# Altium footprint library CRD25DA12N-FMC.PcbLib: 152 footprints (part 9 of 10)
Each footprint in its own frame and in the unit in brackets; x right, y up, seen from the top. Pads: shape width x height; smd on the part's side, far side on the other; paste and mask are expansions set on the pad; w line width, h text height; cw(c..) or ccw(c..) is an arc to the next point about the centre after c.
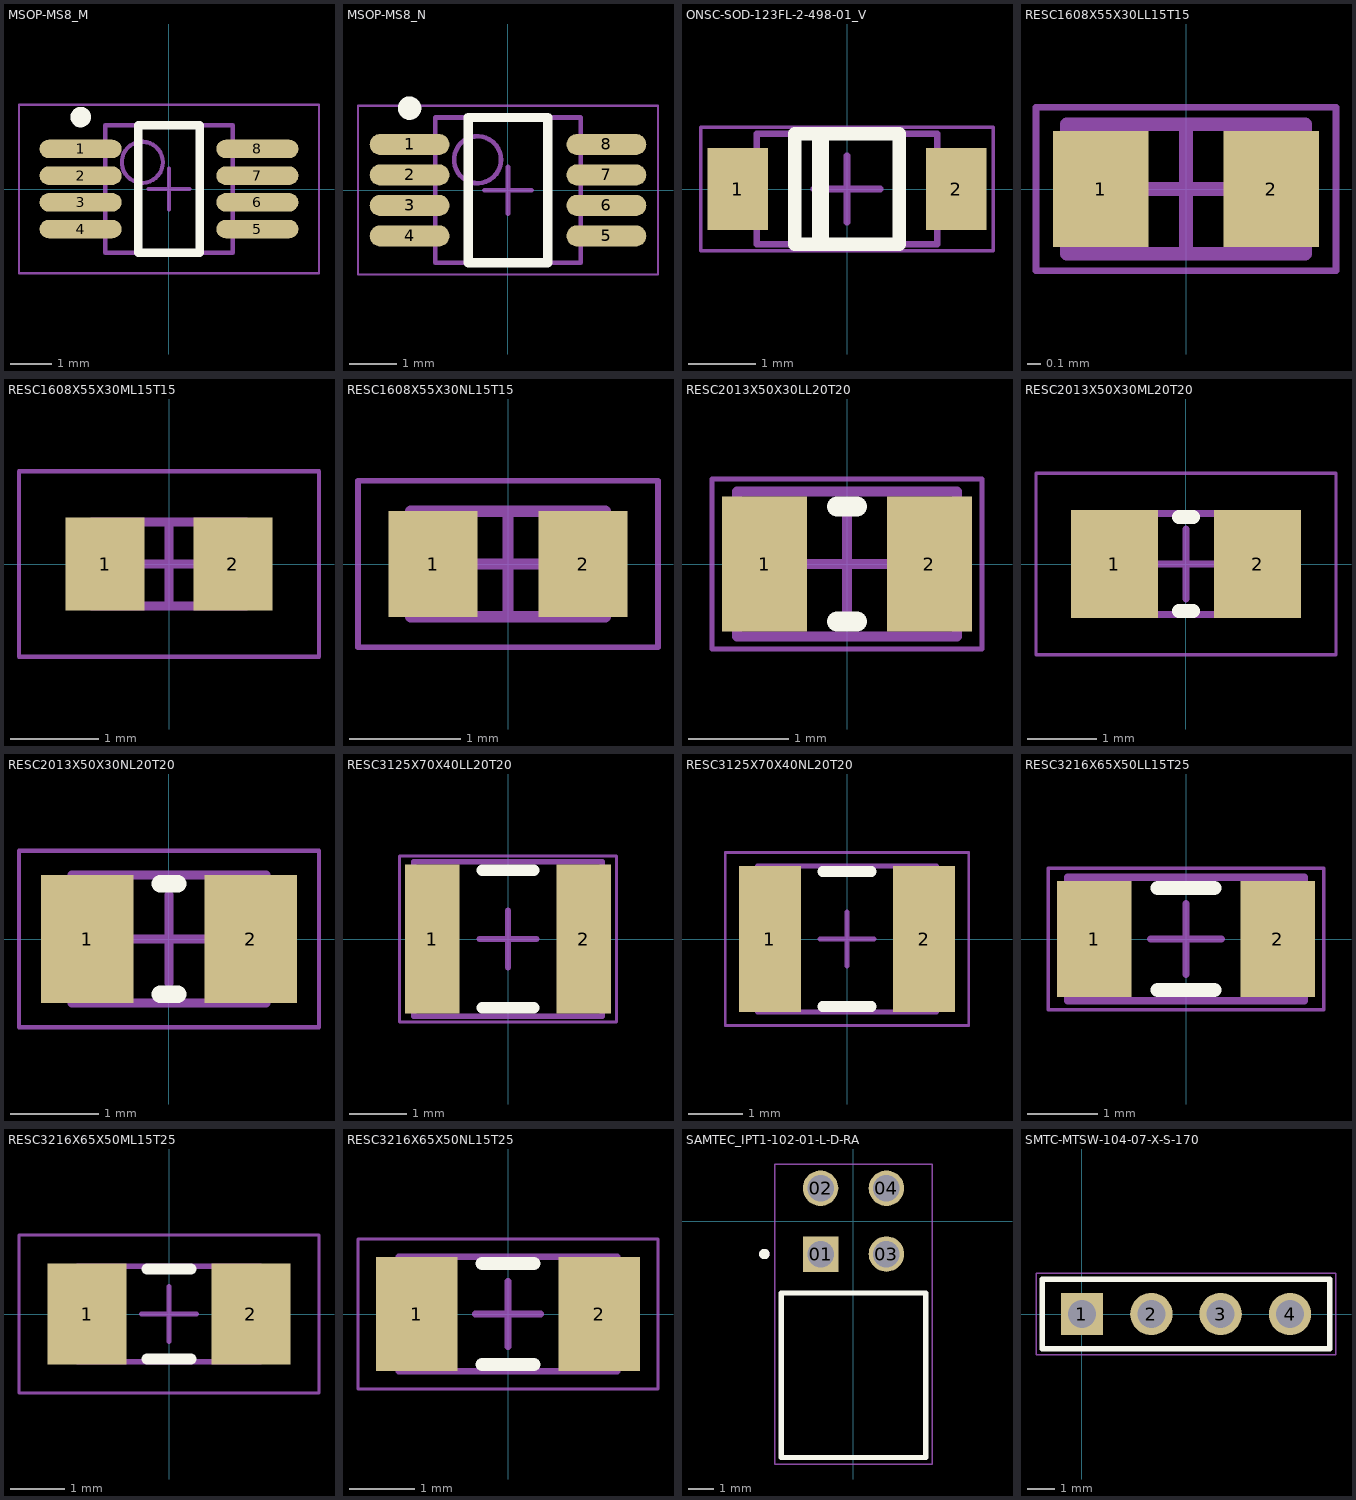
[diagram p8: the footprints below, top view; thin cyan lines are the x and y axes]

## MSOP-MS8_M [mm] "TSOP, 8-Leads, Body 3x3mm, Pitch 0.65mm, IPC Low Density"
height 1.1
pads (8):
  oval 2x0.45 smd: 1(-2.15,0.975) 2(-2.15,0.325) 3(-2.15,-0.325) 4(-2.15,-0.975) 5(2.15,-0.975) 6(2.15,-0.325) 7(2.15,0.325) 8(2.15,0.975)
Top Overlay:
  circle w0.25: c-2.15,1.75 r0.125
  lines w0.2: -0.75,-1.55 -0.75,1.55 0.75,1.55 0.75,-1.55 -0.75,-1.55
Mechanical 13:
  circle w0.1: c-0.65,0.65 r0.5
  lines w0.1: -1.55,-1.55 -1.55,1.55 1.55,1.55 1.55,-1.55 -1.55,-1.55
Mechanical 15:
  lines w0.05: -3.65,-2.05 -3.65,2.05 3.65,2.05 3.65,-2.05 -3.65,-2.05
  lines w0.1: -0.5,0 0.5,0 ; 0,-0.5 0,0.5
3D body: height 1.1, standoff 0, extent -1.55,-1.55 1.55,1.55

## MSOP-MS8_N [mm] "TSOP, 8-Leads, Body 3x3mm, Pitch 0.65mm, IPC Medium Density"
height 1.1
pads (8):
  oval 1.7x0.45 smd: 1(-2.1,0.975) 2(-2.1,0.325) 3(-2.1,-0.325) 4(-2.1,-0.975) 5(2.1,-0.975) 6(2.1,-0.325) 7(2.1,0.325) 8(2.1,0.975)
Top Overlay:
  circle w0.25: c-2.1,1.75 r0.125
  lines w0.2: -0.85,-1.55 0.85,-1.55 0.85,1.55 -0.85,1.55 -0.85,-1.55
Mechanical 13:
  circle w0.1: c-0.65,0.65 r0.5
  lines w0.1: -1.55,-1.55 1.55,-1.55 1.55,1.55 -1.55,1.55 -1.55,-1.55
Mechanical 15:
  lines w0.05: -3.2,-1.8 3.2,-1.8 3.2,1.8 -3.2,1.8 -3.2,-1.8
  lines w0.1: -0.5,0 0.5,0 ; 0,-0.5 0,0.5
3D body: height 1.1, standoff 0, extent -1.55,-1.55 1.55,1.55

## ONSC-SOD-123FL-2-498-01_V [mm] "SOD, 2-Leads, Body 2.7x1.65mm"
height 1
pads (2):
  rect 0.91x1.22 smd: 1(-1.635,0) 2(1.635,0)
Top Overlay:
  lines w0.2: -0.78,-0.825 -0.78,0.825 0.78,0.825 0.78,-0.825 -0.78,-0.825
  lines w0.254: -0.4,-0.78 -0.4,0.78
Mechanical 13:
  lines w0.1: -1.35,-0.825 -1.35,0.825 1.35,0.825 1.35,-0.825 -1.35,-0.825
Mechanical 15:
  lines w0.05: -2.19,-0.925 -2.19,0.925 2.19,0.925 2.19,-0.925 -2.19,-0.925
  lines w0.1: -0.5,0 0.5,0 ; 0,-0.5 0,0.5
3D body: height 1, standoff 0, extent -1.35,-0.825 1.35,0.825

## RESC1608X55X30LL15T15 [mm] "Chip Resistor, 2-Leads, Body 1.60x0.80mm, IPC High Density"
height 0.55
pads (2):
  rect 0.7x0.85 smd: 1(-0.625,0) 2(0.625,0)
Mechanical 13:
  lines w0.1: -0.875,-0.475 0.875,-0.475 0.875,0.475 -0.875,0.475 -0.875,-0.475
Mechanical 15:
  lines w0.05: -1.1,-0.6 1.1,-0.6 1.1,0.6 -1.1,0.6 -1.1,-0.6
  lines w0.1: -0.475,0 0.475,0 ; 0,-0.475 0,0.475
3D body: height 0.55, standoff 0, extent 0.575,-0.475 0.875,0.475
3D body: height 0.55, standoff 0, extent -0.875,-0.475 -0.575,0.475
3D body: height 0.55, standoff 0, extent -0.575,-0.475 0.575,0.475

## RESC1608X55X30ML15T15 [mm] "Chip Resistor, 2-Leads, Body 1.60x0.80mm, IPC Low Density"
height 0.55
pads (2):
  rect 0.9x1.05 smd: 1(-0.725,0) 2(0.725,0)
Mechanical 13:
  lines w0.1: -0.875,-0.475 0.875,-0.475 0.875,0.475 -0.875,0.475 -0.875,-0.475
Mechanical 15:
  lines w0.05: -1.7,-1.05 1.7,-1.05 1.7,1.05 -1.7,1.05 -1.7,-1.05
  lines w0.1: -0.475,0 0.475,0 ; 0,-0.475 0,0.475
3D body: height 0.55, standoff 0, extent 0.575,-0.475 0.875,0.475
3D body: height 0.55, standoff 0, extent -0.875,-0.475 -0.575,0.475
3D body: height 0.55, standoff 0, extent -0.575,-0.475 0.575,0.475

## RESC1608X55X30NL15T15 [mm] "Chip Resistor, 2-Leads, Body 1.60x0.80mm, IPC Medium Density"
height 0.55
pads (2):
  rect 0.8x0.95 smd: 1(-0.675,0) 2(0.675,0)
Mechanical 13:
  lines w0.1: -0.875,-0.475 0.875,-0.475 0.875,0.475 -0.875,0.475 -0.875,-0.475
Mechanical 15:
  lines w0.05: -1.35,-0.75 1.35,-0.75 1.35,0.75 -1.35,0.75 -1.35,-0.75
  lines w0.1: -0.475,0 0.475,0 ; 0,-0.475 0,0.475
3D body: height 0.55, standoff 0, extent 0.575,-0.475 0.875,0.475
3D body: height 0.55, standoff 0, extent -0.875,-0.475 -0.575,0.475
3D body: height 0.55, standoff 0, extent -0.575,-0.475 0.575,0.475

## RESC2013X50X30LL20T20 [mm] "Chip Resistor, 2-Leads, Body 2.00x1.25mm, IPC High Density"
height 0.5
pads (2):
  rect 0.85x1.35 smd: 1(-0.825,0) 2(0.825,0)
Top Overlay:
  lines w0.2: -0.1,-0.575 0.1,-0.575 ; -0.1,0.575 0.1,0.575
Mechanical 13:
  lines w0.1: -1.1,-0.725 1.1,-0.725 1.1,0.725 -1.1,0.725 -1.1,-0.725
Mechanical 15:
  lines w0.05: -1.35,-0.85 1.35,-0.85 1.35,0.85 -1.35,0.85 -1.35,-0.85
  lines w0.1: -0.5,0 0.5,0 ; 0,-0.5 0,0.5
3D body: height 0.5, standoff 0, extent 0.8,-0.725 1.1,0.725
3D body: height 0.5, standoff 0, extent -1.1,-0.725 -0.8,0.725
3D body: height 0.5, standoff 0, extent -0.8,-0.725 0.8,0.725

## RESC2013X50X30ML20T20 [mm] "Chip Resistor, 2-Leads, Body 2.00x1.25mm, IPC Low Density"
height 0.5
pads (2):
  rect 1.25x1.55 smd: 1(-1.025,0) 2(1.025,0)
Top Overlay:
  lines w0.2: -0.1,-0.675 0.1,-0.675 ; -0.1,0.675 0.1,0.675
Mechanical 13:
  lines w0.1: -1.1,-0.725 1.1,-0.725 1.1,0.725 -1.1,0.725 -1.1,-0.725
Mechanical 15:
  lines w0.05: -2.15,-1.3 2.15,-1.3 2.15,1.3 -2.15,1.3 -2.15,-1.3
  lines w0.1: -0.5,0 0.5,0 ; 0,-0.5 0,0.5
3D body: height 0.5, standoff 0, extent 0.8,-0.725 1.1,0.725
3D body: height 0.5, standoff 0, extent -1.1,-0.725 -0.8,0.725
3D body: height 0.5, standoff 0, extent -0.8,-0.725 0.8,0.725

## RESC2013X50X30NL20T20 [mm] "Chip Resistor, 2-Leads, Body 2.00x1.25mm, IPC Medium Density"
height 0.5
pads (2):
  rect 1.05x1.45 smd: 1(-0.925,0) 2(0.925,0)
Top Overlay:
  lines w0.2: -0.1,-0.625 0.1,-0.625 ; -0.1,0.625 0.1,0.625
Mechanical 13:
  lines w0.1: -1.1,-0.725 -1.1,0.725 1.1,0.725 1.1,-0.725 -1.1,-0.725
Mechanical 15:
  lines w0.05: -1.7,-1 -1.7,1 1.7,1 1.7,-1 -1.7,-1
  lines w0.1: -0.5,0 0.5,0 ; 0,-0.5 0,0.5
3D body: height 0.5, standoff 0, extent -0.8,-0.725 0.8,0.725
3D body: height 0.5, standoff 0, extent -1.1,-0.725 -0.8,0.725
3D body: height 0.5, standoff 0, extent 0.8,-0.725 1.1,0.725

## RESC3125X70X40LL20T20 [mm] "Chip Resistor, 2-Leads, Body 3.10x2.50mm, IPC High Density"
height 0.7
pads (2):
  rect 0.95x2.6 smd: 1(-1.325,0) 2(1.325,0)
Top Overlay:
  lines w0.2: -0.45,-1.2 0.45,-1.2 ; -0.45,1.2 0.45,1.2
Mechanical 13:
  lines w0.1: -1.65,-1.35 1.65,-1.35 1.65,1.35 -1.65,1.35 -1.65,-1.35
Mechanical 15:
  lines w0.05: -1.9,-1.45 1.9,-1.45 1.9,1.45 -1.9,1.45 -1.9,-1.45
  lines w0.1: -0.5,0 0.5,0 ; 0,-0.5 0,0.5
3D body: height 0.7, standoff 0, extent 1.25,-1.35 1.65,1.35
3D body: height 0.7, standoff 0, extent -1.65,-1.35 -1.25,1.35
3D body: height 0.7, standoff 0, extent -1.25,-1.35 1.25,1.35

## RESC3125X70X40NL20T20 [mm] "Chip Resistor, 2-Leads, Body 3.10x2.50mm, IPC Medium Density"
height 0.7
pads (2):
  rect 1.15x2.7 smd: 1(-1.425,0) 2(1.425,0)
Top Overlay:
  lines w0.2: -0.45,-1.25 0.45,-1.25 ; -0.45,1.25 0.45,1.25
Mechanical 13:
  lines w0.1: -1.65,-1.35 -1.65,1.35 1.65,1.35 1.65,-1.35 -1.65,-1.35
Mechanical 15:
  lines w0.05: -2.25,-1.6 -2.25,1.6 2.25,1.6 2.25,-1.6 -2.25,-1.6
  lines w0.1: -0.5,0 0.5,0 ; 0,-0.5 0,0.5
3D body: height 0.7, standoff 0, extent -1.25,-1.35 1.25,1.35
3D body: height 0.7, standoff 0, extent -1.65,-1.35 -1.25,1.35
3D body: height 0.7, standoff 0, extent 1.25,-1.35 1.65,1.35

## RESC3216X65X50LL15T25 [mm] "Chip Resistor, 2-Leads, Body 3.20x1.60mm, IPC High Density"
height 0.65
pads (2):
  rect 1.05x1.65 smd: 1(-1.3,0) 2(1.3,0)
Top Overlay:
  lines w0.2: -0.4,-0.725 0.4,-0.725 ; -0.4,0.725 0.4,0.725
Mechanical 13:
  lines w0.1: -1.675,-0.875 -1.675,0.875 1.675,0.875 1.675,-0.875 -1.675,-0.875
Mechanical 15:
  lines w0.05: -1.95,-1 -1.95,1 1.95,1 1.95,-1 -1.95,-1
  lines w0.1: -0.5,0 0.5,0 ; 0,-0.5 0,0.5
3D body: height 0.65, standoff 0, extent -1.175,-0.875 1.175,0.875
3D body: height 0.65, standoff 0, extent -1.675,-0.875 -1.175,0.875
3D body: height 0.65, standoff 0, extent 1.175,-0.875 1.675,0.875

## RESC3216X65X50ML15T25 [mm] "Chip Resistor, 2-Leads, Body 3.20x1.60mm, IPC Low Density"
height 0.65
pads (2):
  rect 1.45x1.85 smd: 1(-1.5,0) 2(1.5,0)
Top Overlay:
  lines w0.2: -0.4,-0.825 0.4,-0.825 ; -0.4,0.825 0.4,0.825
Mechanical 13:
  lines w0.1: -1.675,-0.875 -1.675,0.875 1.675,0.875 1.675,-0.875 -1.675,-0.875
Mechanical 15:
  lines w0.05: -2.75,-1.45 -2.75,1.45 2.75,1.45 2.75,-1.45 -2.75,-1.45
  lines w0.1: -0.5,0 0.5,0 ; 0,-0.5 0,0.5
3D body: height 0.65, standoff 0, extent -1.175,-0.875 1.175,0.875
3D body: height 0.65, standoff 0, extent -1.675,-0.875 -1.175,0.875
3D body: height 0.65, standoff 0, extent 1.175,-0.875 1.675,0.875

## RESC3216X65X50NL15T25 [mm] "Chip Resistor, 2-Leads, Body 3.20x1.60mm, IPC Medium Density"
height 0.65
pads (2):
  rect 1.25x1.75 smd: 1(-1.4,0) 2(1.4,0)
Top Overlay:
  lines w0.2: -0.4,-0.775 0.4,-0.775 ; -0.4,0.775 0.4,0.775
Mechanical 13:
  lines w0.1: -1.675,-0.875 1.675,-0.875 1.675,0.875 -1.675,0.875 -1.675,-0.875
Mechanical 15:
  lines w0.05: -2.3,-1.15 2.3,-1.15 2.3,1.15 -2.3,1.15 -2.3,-1.15
  lines w0.1: -0.5,0 0.5,0 ; 0,-0.5 0,0.5
3D body: height 0.65, standoff 0, extent 1.175,-0.875 1.675,0.875
3D body: height 0.65, standoff 0, extent -1.675,-0.875 -1.175,0.875
3D body: height 0.65, standoff 0, extent -1.175,-0.875 1.175,0.875

## SAMTEC_IPT1-102-01-L-D-RA [mm]
pads (4):
  rect 1.37x1.37 / inner round 1.37 / far side rect 1.37x1.37 hole 1.02: 01(-1.27,-1.27)
  round 1.37 hole 1.02: 02(-1.27,1.27) 03(1.27,-1.27) 04(1.27,1.27)
Top Overlay:
  circle w0.2: c-3.44,-1.27 r0.1
  lines w0.2: -2.79,-9.12 -2.79,-2.77 2.79,-2.77 2.79,-9.12 -2.79,-9.12
Mechanical 13:
  circle w0.2: c-3.44,-1.27 r0.1
  lines w0.1: -2.79,-9.12 -2.79,-2.77 2.79,-2.77 2.79,-9.12 ; -2.79,-9.12 2.79,-9.12 ; -2.79,-9.12 2.79,-9.12
Mechanical 15:
  lines w0.05: -3.04,-9.37 -3.04,2.205 3.04,2.205 3.04,-9.37 -3.04,-9.37
3D body "IPT1-102-01-L-D-RA.stp": height 5.14, standoff -2.23, extent -2.794,-9.15 2.794,1.582

## SMTC-MTSW-104-07-X-S-170 [mm] "Assembly .025\" [.64] SQ Post Terminal Strip, 1x4 Pins, Vertical, 2.54mm Pitch, Male"
height 7.061
pads (4):
  rect 1.55x1.55 hole 1.02: 1(0,0)
  round 1.55 hole 1.02: 2(2.54,0) 3(5.08,0) 4(7.62,0)
Top Overlay:
  lines w0.2: -1.46,-1.27 -1.46,1.27 9.08,1.27 9.08,-1.27 -1.46,-1.27
Mechanical 13:
  lines w0.1: -1.46,-1.27 -1.46,1.27 9.08,1.27 9.08,-1.27 -1.46,-1.27
Mechanical 15:
  lines w0.05: -1.685,-1.495 -1.685,1.495 9.305,1.495 9.305,-1.495 -1.685,-1.495
3D body "MTSW-104-07-X-S-170.step": height 6.86, standoff -4.06, extent -1.27,-1.27 8.89,1.27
